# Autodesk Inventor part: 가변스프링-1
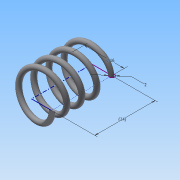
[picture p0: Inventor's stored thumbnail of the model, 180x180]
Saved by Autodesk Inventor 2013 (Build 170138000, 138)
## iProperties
Created: 2015-09
Part Number: 가변스프링-1
Material: 일반
Document SubType Name: Modeling
Designer: Administrator
Density: 1 g/cm^3
Mass: 0.625488 g
Surface Area: 12.7485 cm^2
Volume: 0.625488 cm^3
Author: Administrator
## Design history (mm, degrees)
sketch "스케치1"
  geometry: L1 (0, 0)-(8, 0); L2 (8, 0)-(8, 42); L3 (8, 42)-(0, 42); L4 (0, 42)-(0, 0); C1 r 1 at (8, 42)
  constraints: 8 end point, 2 parallel, 1 centre point, 1 coincident, 1 horizontal, 1 perpendicular
  dimensions: "d0" = 16 diameter of L2 L4; "d2" = 42 distance between parallel lines of L1 L3 (derived); "d3" = 2 diameter of C1
feature "코일1" pitch "d4" = 10; turns "d6" = 4; dims "d5" = 42 (= d2), "d7" = 0, angle "d8" = 90 deg, angle "d9" = 90 deg, "d10" = 0, "d11" = 0
feature "분할1"
node "작업 평면1"
feature "분할2"
node "솔리드1"
other parameters: "d12" = 90 deg
